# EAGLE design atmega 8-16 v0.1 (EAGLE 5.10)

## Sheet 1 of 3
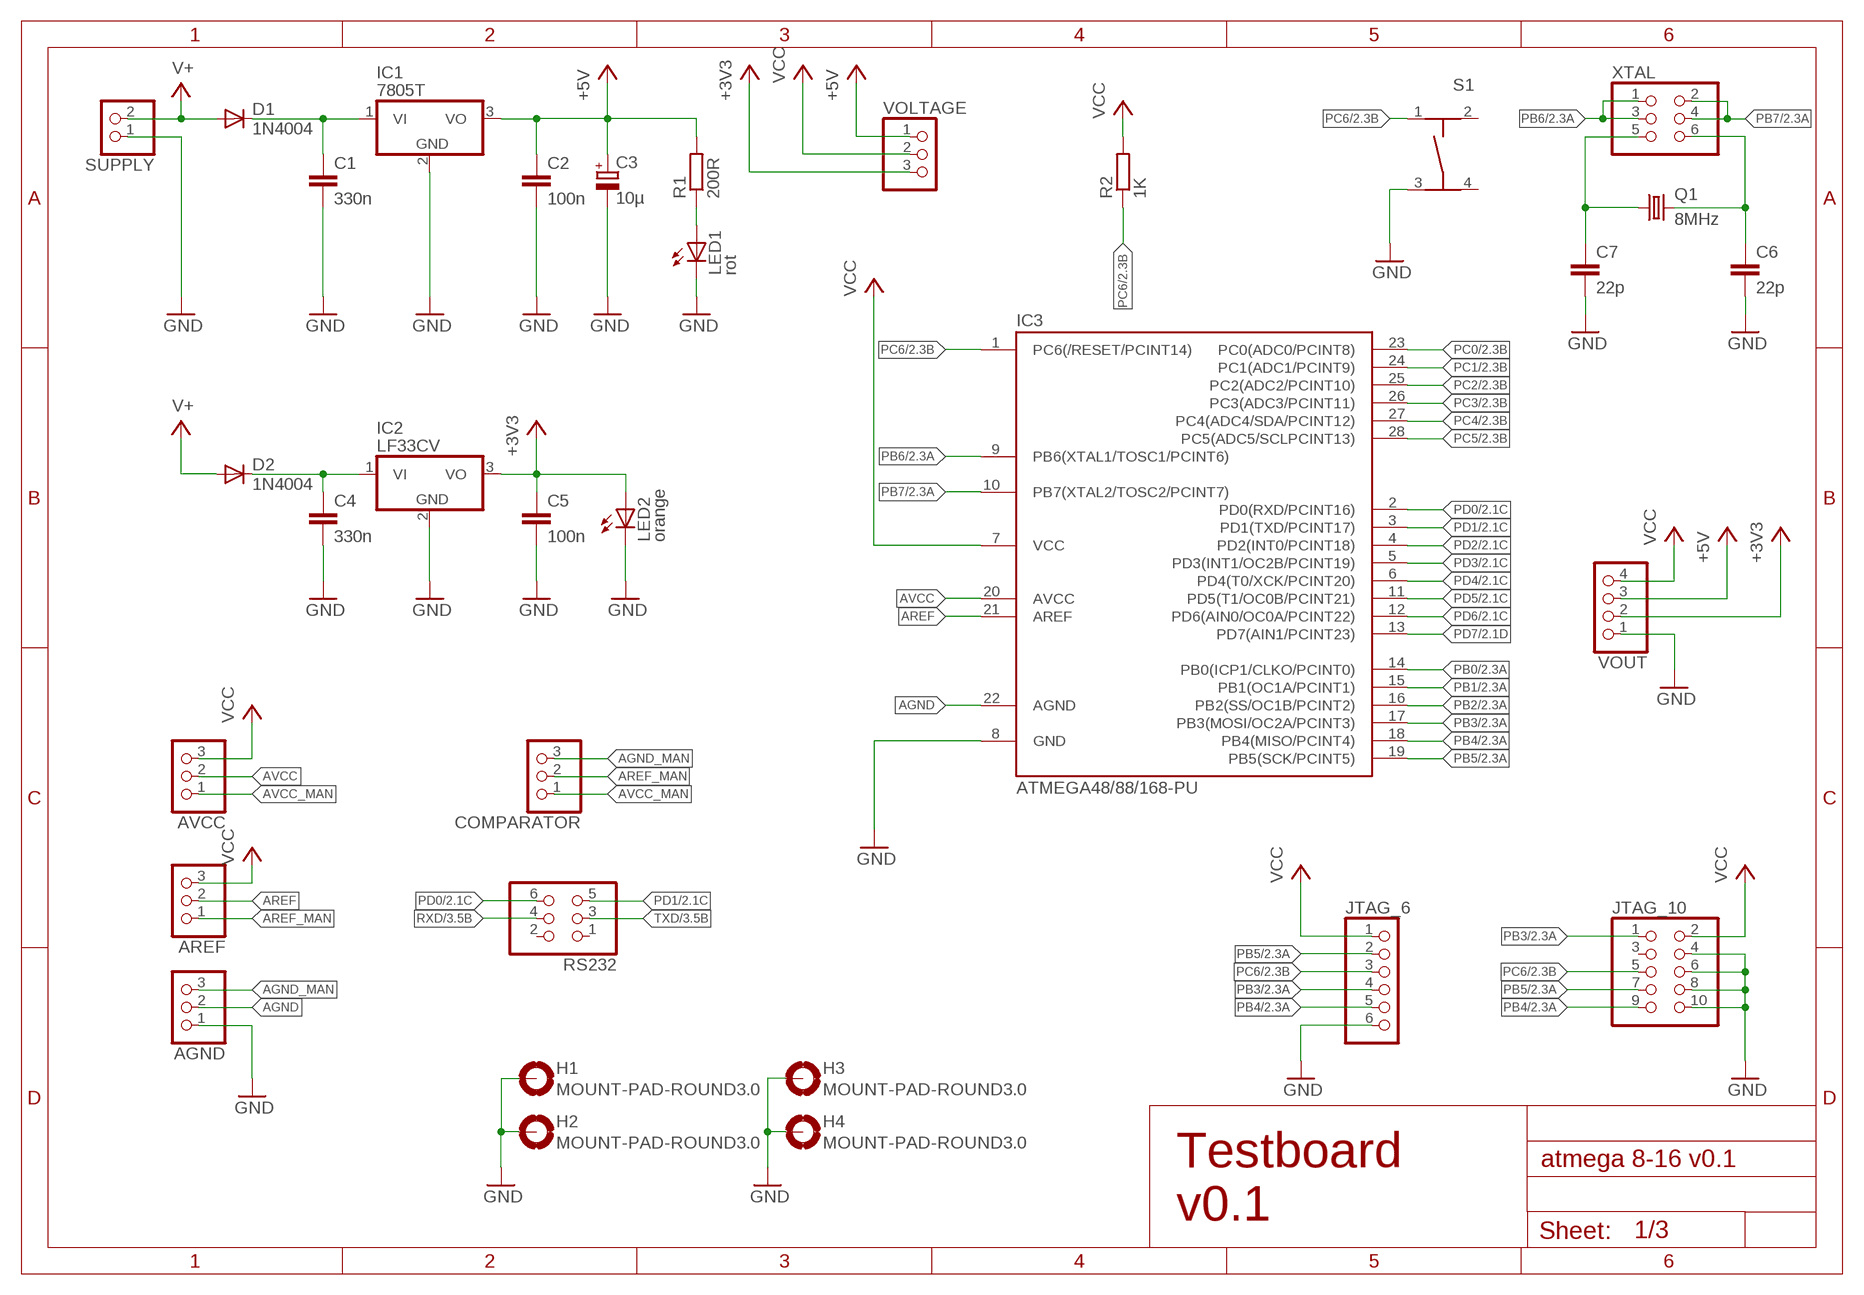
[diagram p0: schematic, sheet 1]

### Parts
AGND  PINHD-1X3  [1X03]
AREF  PINHD-1X3  [1X03]
AVCC  PINHD-1X3  [1X03]
C1  330n  C-EU025-030X050  [C025-030X050]
C2  100n  C-EU025-030X050  [C025-030X050]
C3  10µ  CPOL-EUE2.5-5  [E2,5-5]
C4  330n  C-EU025-030X050  [C025-030X050]
C5  100n  C-EU025-030X050  [C025-030X050]
C6  22p  C-EU025-030X050  [C025-030X050]
C7  22p  C-EU025-030X050  [C025-030X050]
COMPARATOR  PINHD-1X3  [1X03]
D1  1N4004  [DO41-10]
D2  1N4004  [DO41-10]
H1  MOUNT-PAD-ROUND3.0  [3,0-PAD]
H2  MOUNT-PAD-ROUND3.0  [3,0-PAD]
H3  MOUNT-PAD-ROUND3.0  [3,0-PAD]
H4  MOUNT-PAD-ROUND3.0  [3,0-PAD]
IC1  7805T  [TO220H]
IC2  LF33CV  7805T  [TO220H]
IC3  ATMEGA48/88/168-PU  [DIL28-3]
JTAG_6  PINHD-1X6  [1X06]
JTAG_10  PINHD-2X5  [2X05]
LED1  rot  LED3MM  [LED3MM]
LED2  orange  LED3MM  [LED3MM]
Q1  8MHz  CRYSTALHC18U-V  [HC18U-V]
R1  200R  R-EU_0207/12  [0207/12]
R2  1K  R-EU_0207/12  [0207/12]
RS232  PINHD-2X3  [2X03]
S1  TASTER-9314_SMD  [TASTER-9314_SMD]
SUPPLY  PINHD-1X2  [1X02]
VOLTAGE  PINHD-1X3  [1X03]
VOUT  PINHD-1X4  [1X04]
XTAL  PINHD-2X3  [2X03]

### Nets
+3V3: C5.1 IC2.3(VO) LED2.A VOLTAGE.3 VOUT.2
+5V: C2.1 C3.+ IC1.3(VO) R1.2 VOLTAGE.1 VOUT.3 ; also sheet 3
AGND: AGND.2 IC3.22(AGND)
AGND_MAN: AGND.3 COMPARATOR.3
AREF: AREF.2 IC3.21(AREF)
AREF_MAN: AREF.1 COMPARATOR.2
AVCC: AVCC.2 IC3.20(AVCC)
AVCC_MAN: AVCC.1 COMPARATOR.1
GND: AGND.1 C1.2 C2.2 C3.- C4.2 C5.2 C6.2 C7.2 H1.B3,0(MOUNT) H2.B3,0(MOUNT) H3.B3,0(MOUNT) H4.B3,0(MOUNT) IC1.2(GND) IC2.2(GND) IC3.8(GND) JTAG_6.6 JTAG_10.4 JTAG_10.6 JTAG_10.8 JTAG_10.10 LED1.K(C) LED2.K(C) S1.3 SUPPLY.1 VOUT.1 ; also sheet 2,3
N$1: C4.1 D2.C IC2.1(VI)
N$3: C7.1 Q1.1 XTAL.5
N$4: C1.1 D1.C IC1.1(VI)
N$5: LED1.A R1.1
N$6: C6.1 Q1.2 XTAL.6
PB0: IC3.14(PB0(ICP1/CLKO/PCINT0)) ; also sheet 2
PB1: IC3.15(PB1(OC1A/PCINT1)) ; also sheet 2
PB2: IC3.16(PB2(SS/OC1B/PCINT2)) ; also sheet 2
PB3: IC3.17(PB3(MOSI/OC2A/PCINT3)) JTAG_6.4 JTAG_10.1 ; also sheet 2
PB4: IC3.18(PB4(MISO/PCINT4)) JTAG_6.5 JTAG_10.9 ; also sheet 2
PB5: IC3.19(PB5(SCK/PCINT5)) JTAG_6.2 JTAG_10.7 ; also sheet 2
PB6: IC3.9(PB6(XTAL1/TOSC1/PCINT6)) XTAL.1 XTAL.3 ; also sheet 2
PB7: IC3.10(PB7(XTAL2/TOSC2/PCINT7)) XTAL.2 XTAL.4 ; also sheet 2
PC0: IC3.23(PC0(ADC0/PCINT8)) ; also sheet 2,3
PC1: IC3.24(PC1(ADC1/PCINT9)) ; also sheet 2,3
PC2: IC3.25(PC2(ADC2/PCINT10)) ; also sheet 2,3
PC3: IC3.26(PC3(ADC3/PCINT11)) ; also sheet 2,3
PC4: IC3.27(PC4(ADC4/SDA/PCINT12)) ; also sheet 2,3
PC5: IC3.28(PC5(ADC5/SCLPCINT13)) ; also sheet 2,3
PC6: IC3.1(PC6(/RESET/PCINT14)) JTAG_6.3 JTAG_10.5 R2.1 S1.1 ; also sheet 2
PD0: IC3.2(PD0(RXD/PCINT16)) RS232.6 ; also sheet 2
PD1: IC3.3(PD1(TXD/PCINT17)) RS232.5 ; also sheet 2
PD2: IC3.4(PD2(INT0/PCINT18)) ; also sheet 2,3
PD3: IC3.5(PD3(INT1/OC2B/PCINT19)) ; also sheet 2
PD4: IC3.6(PD4(T0/XCK/PCINT20)) ; also sheet 2
PD5: IC3.11(PD5(T1/OC0B/PCINT21)) ; also sheet 2
PD6: IC3.12(PD6(AIN0/OC0A/PCINT22)) ; also sheet 2,3
PD7: IC3.13(PD7(AIN1/PCINT23)) ; also sheet 2,3
RXD: RS232.4 ; also sheet 3
TXD: RS232.3 ; also sheet 3
V+: D1.A D2.A SUPPLY.2
VCC: AREF.3 AVCC.3 IC3.7(VCC) JTAG_6.1 JTAG_10.2 R2.2 VOLTAGE.2 VOUT.4 ; also sheet 3
Unconnected: JTAG_10.3 RS232.1 RS232.2 S1.2 S1.4

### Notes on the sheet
- Testboard
- v0.1

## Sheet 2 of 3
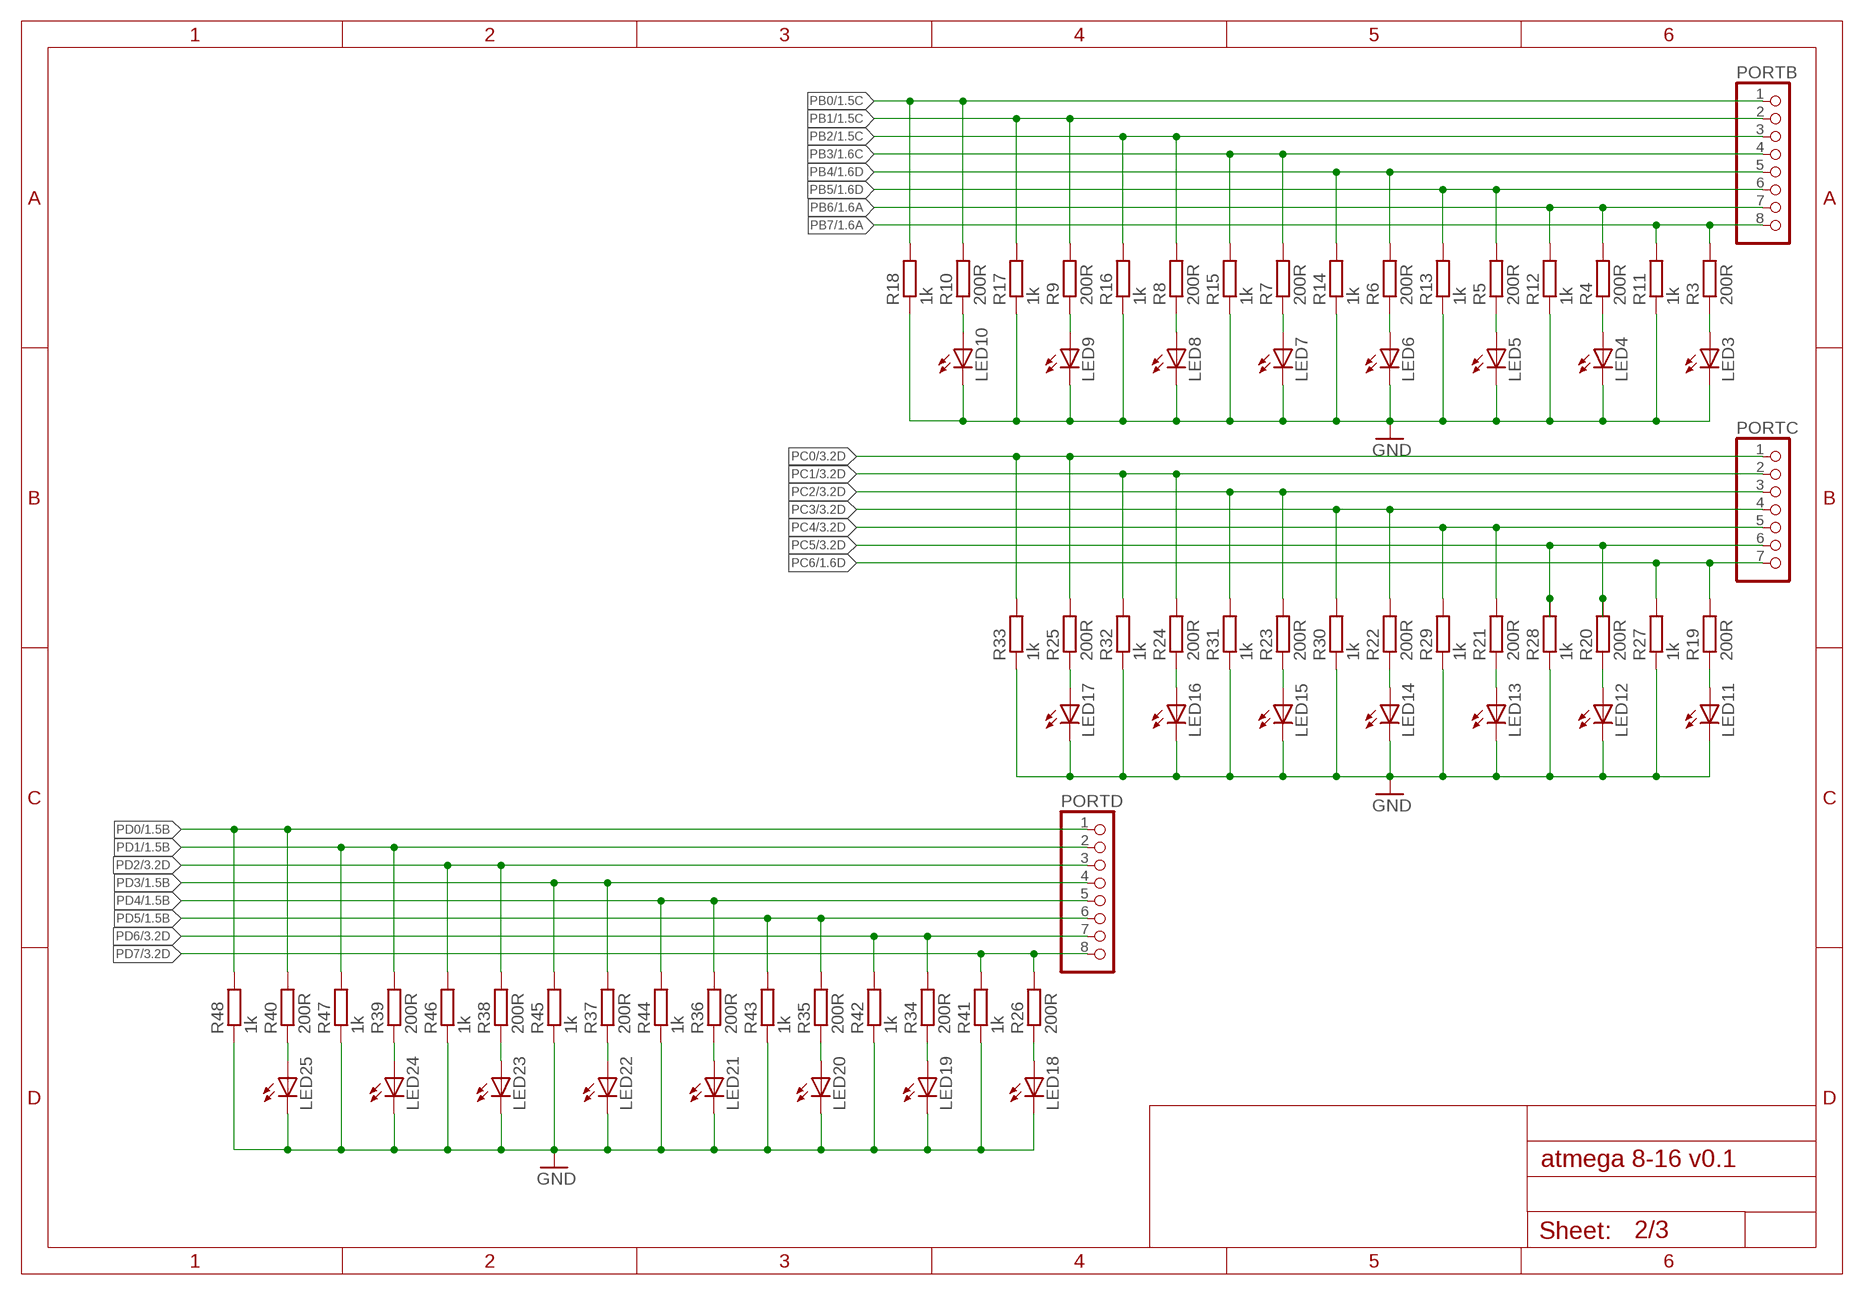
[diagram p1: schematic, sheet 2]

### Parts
LED3  LED3MM  [LED3MM]
LED4  LED3MM  [LED3MM]
LED5  LED3MM  [LED3MM]
LED6  LED3MM  [LED3MM]
LED7  LED3MM  [LED3MM]
LED8  LED3MM  [LED3MM]
LED9  LED3MM  [LED3MM]
LED10  LED3MM  [LED3MM]
LED11  LED3MM  [LED3MM]
LED12  LED3MM  [LED3MM]
LED13  LED3MM  [LED3MM]
LED14  LED3MM  [LED3MM]
LED15  LED3MM  [LED3MM]
LED16  LED3MM  [LED3MM]
LED17  LED3MM  [LED3MM]
LED18  LED3MM  [LED3MM]
LED19  LED3MM  [LED3MM]
LED20  LED3MM  [LED3MM]
LED21  LED3MM  [LED3MM]
LED22  LED3MM  [LED3MM]
LED23  LED3MM  [LED3MM]
LED24  LED3MM  [LED3MM]
LED25  LED3MM  [LED3MM]
PORTB  PINHD-1X8  [1X08]
PORTC  PINHD-1X7  [1X07]
PORTD  PINHD-1X8  [1X08]
R3  200R  R-EU_0207/12  [0207/12]
R4  200R  R-EU_0207/12  [0207/12]
R5  200R  R-EU_0207/12  [0207/12]
R6  200R  R-EU_0207/12  [0207/12]
R7  200R  R-EU_0207/12  [0207/12]
R8  200R  R-EU_0207/12  [0207/12]
R9  200R  R-EU_0207/12  [0207/12]
R10  200R  R-EU_0207/12  [0207/12]
R11  1k  R-EU_0207/12  [0207/12]
R12  1k  R-EU_0207/12  [0207/12]
R13  1k  R-EU_0207/12  [0207/12]
R14  1k  R-EU_0207/12  [0207/12]
R15  1k  R-EU_0207/12  [0207/12]
R16  1k  R-EU_0207/12  [0207/12]
R17  1k  R-EU_0207/12  [0207/12]
R18  1k  R-EU_0207/12  [0207/12]
R19  200R  R-EU_0207/12  [0207/12]
R20  200R  R-EU_0207/12  [0207/12]
R21  200R  R-EU_0207/12  [0207/12]
R22  200R  R-EU_0207/12  [0207/12]
R23  200R  R-EU_0207/12  [0207/12]
R24  200R  R-EU_0207/12  [0207/12]
R25  200R  R-EU_0207/12  [0207/12]
R26  200R  R-EU_0207/12  [0207/12]
R27  1k  R-EU_0207/12  [0207/12]
R28  1k  R-EU_0207/12  [0207/12]
R29  1k  R-EU_0207/12  [0207/12]
R30  1k  R-EU_0207/12  [0207/12]
R31  1k  R-EU_0207/12  [0207/12]
R32  1k  R-EU_0207/12  [0207/12]
R33  1k  R-EU_0207/12  [0207/12]
R34  200R  R-EU_0207/12  [0207/12]
R35  200R  R-EU_0207/12  [0207/12]
R36  200R  R-EU_0207/12  [0207/12]
R37  200R  R-EU_0207/12  [0207/12]
R38  200R  R-EU_0207/12  [0207/12]
R39  200R  R-EU_0207/12  [0207/12]
R40  200R  R-EU_0207/12  [0207/12]
R41  1k  R-EU_0207/12  [0207/12]
R42  1k  R-EU_0207/12  [0207/12]
R43  1k  R-EU_0207/12  [0207/12]
R44  1k  R-EU_0207/12  [0207/12]
R45  1k  R-EU_0207/12  [0207/12]
R46  1k  R-EU_0207/12  [0207/12]
R47  1k  R-EU_0207/12  [0207/12]
R48  1k  R-EU_0207/12  [0207/12]

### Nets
GND: LED3.K(C) LED4.K(C) LED5.K(C) LED6.K(C) LED7.K(C) LED8.K(C) LED9.K(C) LED10.K(C) LED11.K(C) LED12.K(C) LED13.K(C) LED14.K(C) LED15.K(C) LED16.K(C) LED17.K(C) LED18.K(C) LED19.K(C) LED20.K(C) LED21.K(C) LED22.K(C) LED23.K(C) LED24.K(C) LED25.K(C) R11.1 R12.1 R13.1 R14.1 R15.1 R16.1 R17.1 R18.1 R27.1 R28.1 R29.1 R30.1 R31.1 R32.1 R33.1 R41.1 R42.1 R43.1 R44.1 R45.1 R46.1 R47.1 R48.1 ; also sheet 1,3
N$7: LED7.A R7.1
N$8: LED9.A R9.1
N$9: LED10.A R10.1
N$10: LED8.A R8.1
N$11: LED6.A R6.1
N$12: LED5.A R5.1
N$13: LED4.A R4.1
N$14: LED3.A R3.1
N$16: LED15.A R23.1
N$17: LED17.A R25.1
N$18: LED22.A R37.1
N$19: LED16.A R24.1
N$20: LED14.A R22.1
N$21: LED13.A R21.1
N$22: LED12.A R20.1
N$23: LED11.A R19.1
N$25: LED24.A R39.1
N$26: LED25.A R40.1
N$27: LED23.A R38.1
N$28: LED21.A R36.1
N$29: LED20.A R35.1
N$30: LED19.A R34.1
N$31: LED18.A R26.1
PB0: PORTB.1 R10.2 R18.2 ; also sheet 1
PB1: PORTB.2 R9.2 R17.2 ; also sheet 1
PB2: PORTB.3 R8.2 R16.2 ; also sheet 1
PB3: PORTB.4 R7.2 R15.2 ; also sheet 1
PB4: PORTB.5 R6.2 R14.2 ; also sheet 1
PB5: PORTB.6 R5.2 R13.2 ; also sheet 1
PB6: PORTB.7 R4.2 R12.2 ; also sheet 1
PB7: PORTB.8 R3.2 R11.2 ; also sheet 1
PC0: PORTC.1 R25.2 R33.2 ; also sheet 1,3
PC1: PORTC.2 R24.2 R32.2 ; also sheet 1,3
PC2: PORTC.3 R23.2 R31.2 ; also sheet 1,3
PC3: PORTC.4 R22.2 R30.2 ; also sheet 1,3
PC4: PORTC.5 R21.2 R29.2 ; also sheet 1,3
PC5: PORTC.6 R20.2 R28.2 ; also sheet 1,3
PC6: PORTC.7 R19.2 R27.2 ; also sheet 1
PD0: PORTD.1 R40.2 R48.2 ; also sheet 1
PD1: PORTD.2 R39.2 R47.2 ; also sheet 1
PD2: PORTD.3 R38.2 R46.2 ; also sheet 1,3
PD3: PORTD.4 R37.2 R45.2 ; also sheet 1
PD4: PORTD.5 R36.2 R44.2 ; also sheet 1
PD5: PORTD.6 R35.2 R43.2 ; also sheet 1
PD6: PORTD.7 R34.2 R42.2 ; also sheet 1,3
PD7: PORTD.8 R26.2 R41.2 ; also sheet 1,3

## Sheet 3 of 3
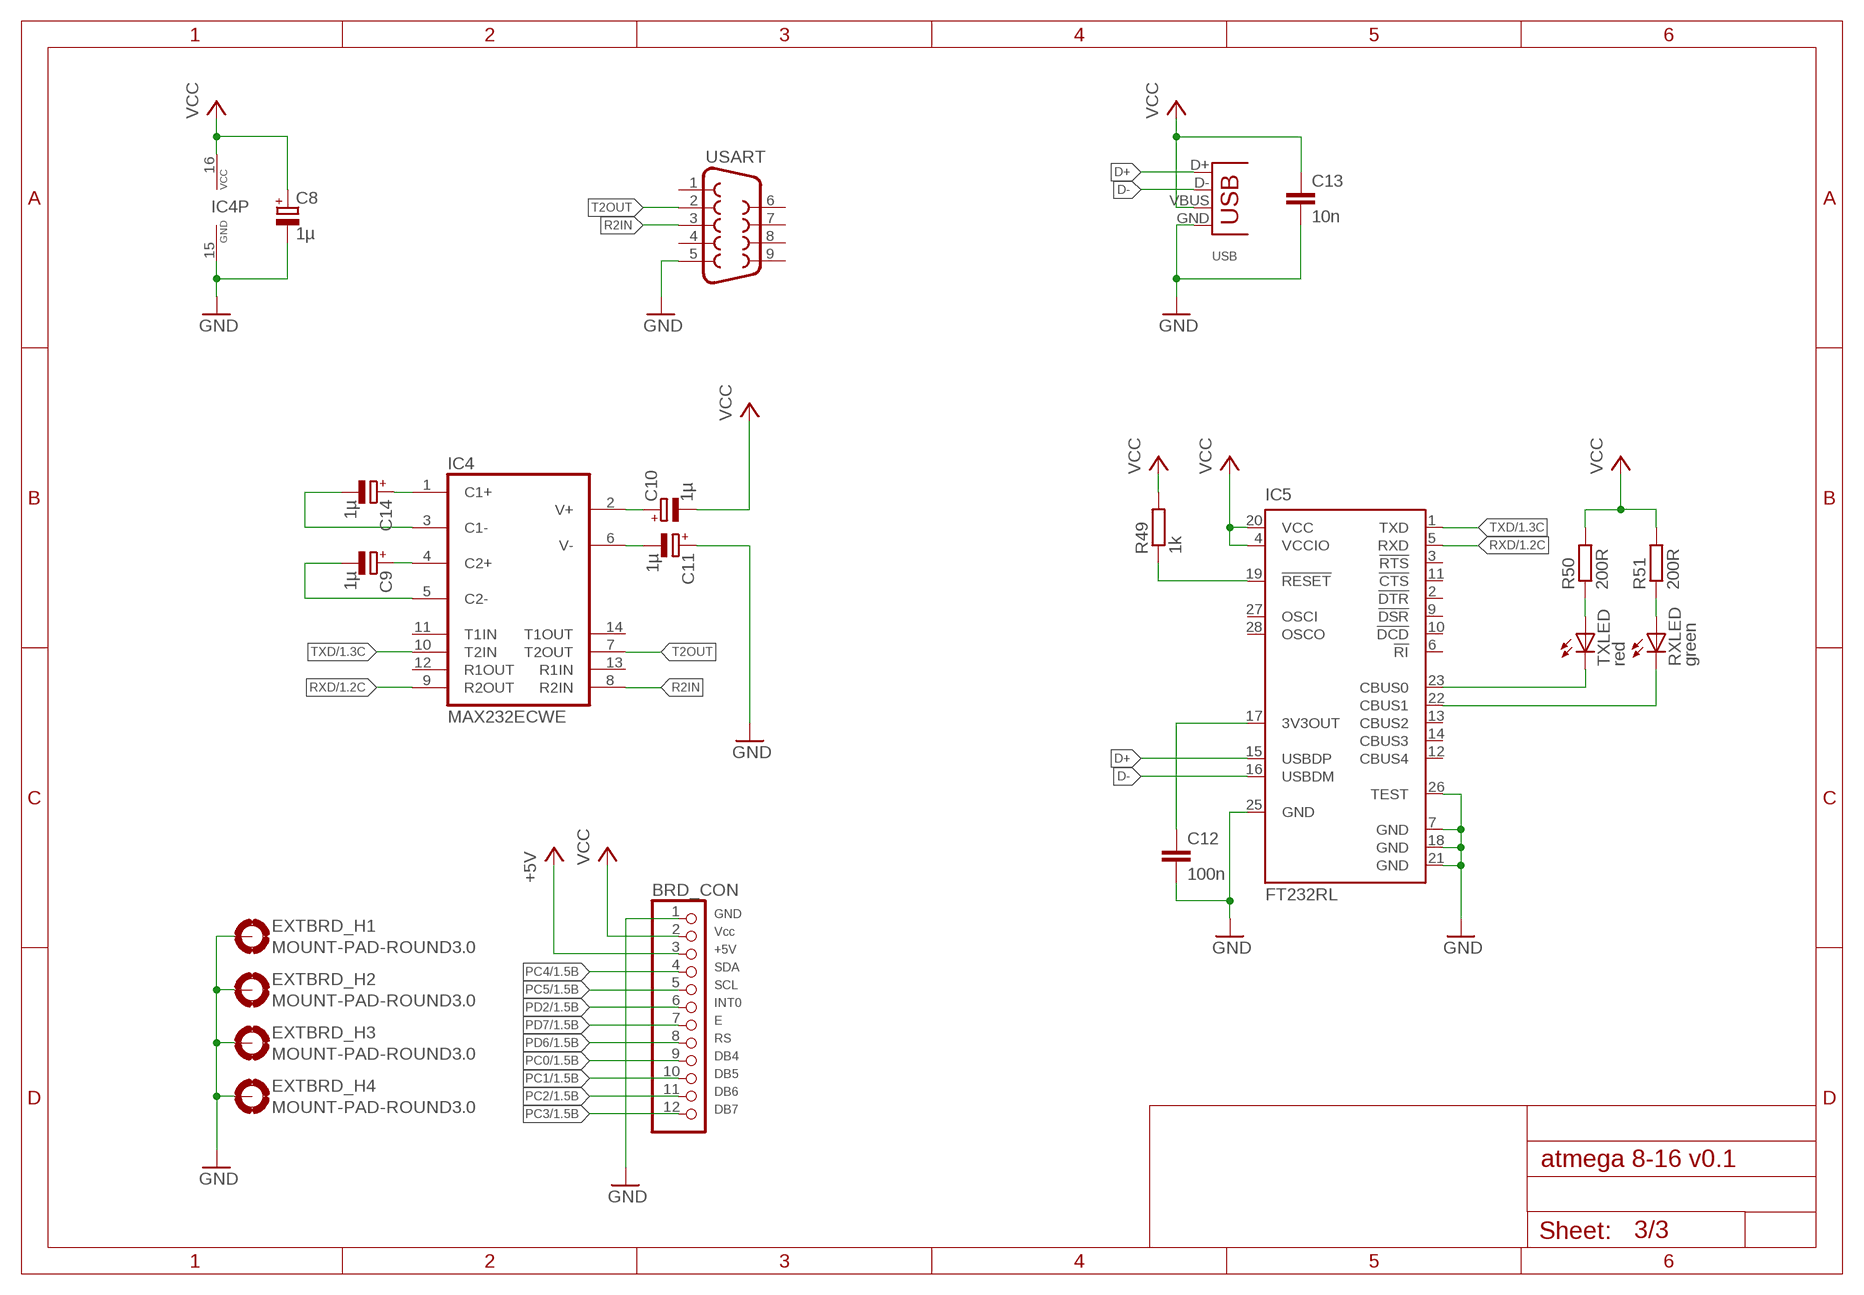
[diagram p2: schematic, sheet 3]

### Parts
BRD_CON  PINHD-1X12  [1X12]
C8  1µ  CPOL-EUE2.5-5  [E2,5-5]
C9  1µ  CPOL-EUE2.5-5  [E2,5-5]
C10  1µ  CPOL-EUE2.5-5  [E2,5-5]
C11  1µ  CPOL-EUE2.5-5  [E2,5-5]
C12  100n  C-EU025-040X050  [C025-040X050]
C13  10n  C-EU025-040X050  [C025-040X050]
C14  1µ  CPOL-EUE2.5-5  [E2,5-5]
EXTBRD_H1  MOUNT-PAD-ROUND3.0  [3,0-PAD]
EXTBRD_H2  MOUNT-PAD-ROUND3.0  [3,0-PAD]
EXTBRD_H3  MOUNT-PAD-ROUND3.0  [3,0-PAD]
EXTBRD_H4  MOUNT-PAD-ROUND3.0  [3,0-PAD]
IC4  MAX232ECWE  [SO16L]
IC5  FT232RL  [SSOP28]
R49  1k  R-EU_0207/2V  [0207/2V]
R50  200R  R-EU_0207/12  [0207/12]
R51  200R  R-EU_0207/12  [0207/12]
RXLED  green  LED3MM  [LED3MM]
TXLED  red  LED3MM  [LED3MM]
USART  F09HP  [F09HP]
USB  USB-B-H  [USB-B-H]

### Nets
+5V: BRD_CON.3 ; also sheet 1
D+: IC5.15(USBDP) USB.D+
D-: IC5.16(USBDM) USB.D-
GND: BRD_CON.1 C8.- C11.+ C12.2 C13.2 EXTBRD_H1.B3,0(MOUNT) EXTBRD_H2.B3,0(MOUNT) EXTBRD_H3.B3,0(MOUNT) EXTBRD_H4.B3,0(MOUNT) IC4.15(GND) IC5.7(GND) IC5.18(GND) IC5.21(GND) IC5.25(GND) IC5.26(TEST) USART.5 USB.GND ; also sheet 1,2
N$2: C14.- IC4.3(C1-)
N$15: C14.+ IC4.1(C1+)
N$33: C10.+ IC4.2(V+)
N$34: C11.- IC4.6(V-)
N$35: C9.+ IC4.4(C2+)
N$36: C9.- IC4.5(C2-)
N$37: IC5.19(!RESET) R49.1
N$38: C12.1 IC5.17(3V3OUT)
N$41: R50.1 TXLED.A
N$42: R51.1 RXLED.A
N$43: IC5.23(CBUS0) TXLED.K(C)
N$44: IC5.22(CBUS1) RXLED.K(C)
PC0: BRD_CON.9 ; also sheet 1,2
PC1: BRD_CON.10 ; also sheet 1,2
PC2: BRD_CON.11 ; also sheet 1,2
PC3: BRD_CON.12 ; also sheet 1,2
PC4: BRD_CON.4 ; also sheet 1,2
PC5: BRD_CON.5 ; also sheet 1,2
PD2: BRD_CON.6 ; also sheet 1,2
PD6: BRD_CON.8 ; also sheet 1,2
PD7: BRD_CON.7 ; also sheet 1,2
R2IN: IC4.8(R2IN) USART.3
RXD: IC4.9(R2OUT) IC5.5(RXD) ; also sheet 1
T2OUT: IC4.7(T2OUT) USART.2
TXD: IC4.10(T2IN) IC5.1(TXD) ; also sheet 1
VCC: BRD_CON.2 C8.+ C10.- C13.1 IC4.16(VCC) IC5.4(VCCIO) IC5.20(VCC) R49.2 R50.2 R51.2 USB.VBUS ; also sheet 1
Unconnected: IC4.11(T1IN) IC4.12(R1OUT) IC4.13(R1IN) IC4.14(T1OUT) IC5.2(!DTR) IC5.3(!RTS) IC5.6(!RI) IC5.9(!DSR) IC5.10(!DCD) IC5.11(!CTS) IC5.12(CBUS4) IC5.13(CBUS2) IC5.14(CBUS3) IC5.27(OSCI) IC5.28(OSCO) USART.1 USART.4 USART.6 USART.7 USART.8 USART.9

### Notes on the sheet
- GND
- Vcc
- +5V
- SDA
- SCL
- INT0
- E
- RS
- DB4
- DB5
- DB6
- DB7

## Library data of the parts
AGND AREF AVCC COMPARATOR VOLTAGE = pinhead:PINHD-1X3: PIN HEADER
BRD_CON = pinhead:PINHD-1X12: PIN HEADER
C1 C2 C4-C7 C12 C13 = rcl:C-EU: CAPACITOR, European symbol
C3 C8-C11 C14 = rcl:CPOL-EU: POLARIZED CAPACITOR, European symbol
D1 D2 = diode:1N4004: DIODE
EXTBRD_H1-EXTBRD_H4 H1-H4 = holes:MOUNT-PAD-ROUND: MOUNTING PAD, round
IC1 IC2 = linear:78*: Positive VOLTAGE REGULATOR Source: http://cache.national.com/ds/LM/LM78L05.pdf http://www.fairchildsemi.com/ds/LM/LM7805.pdf
IC3 = atmega8:ATMEGA48/88/168-PU
IC4 = maxim:MAX232ECWE: RS232 TRANSEIVER
IC5 = ftdichip:FT232R: Source: http://www.ftdichip.com/Documents/DataSheets/DS_FT232R_v104.pdf
JTAG_6 = pinhead:PINHD-1X6: PIN HEADER
JTAG_10 = pinhead:PINHD-2X5: PIN HEADER
LED1-LED25 RXLED TXLED = led:LED: LED
PORTB PORTD = pinhead:PINHD-1X8: PIN HEADER
PORTC = pinhead:PINHD-1X7: PIN HEADER
Q1 = crystal:CRYSTAL: CRYSTAL
R1-R51 = rcl:R-EU_: RESISTOR, European symbol
RS232 XTAL = pinhead:PINHD-2X3: PIN HEADER
S1 = Ergaenzung_Taster:TASTER-9314_SMD
SUPPLY = pinhead:PINHD-1X2: PIN HEADER
USART = con-subd:F09: SUB-D
USB = con-usb-3:USB: USB Connectors
VOUT = pinhead:PINHD-1X4: PIN HEADER

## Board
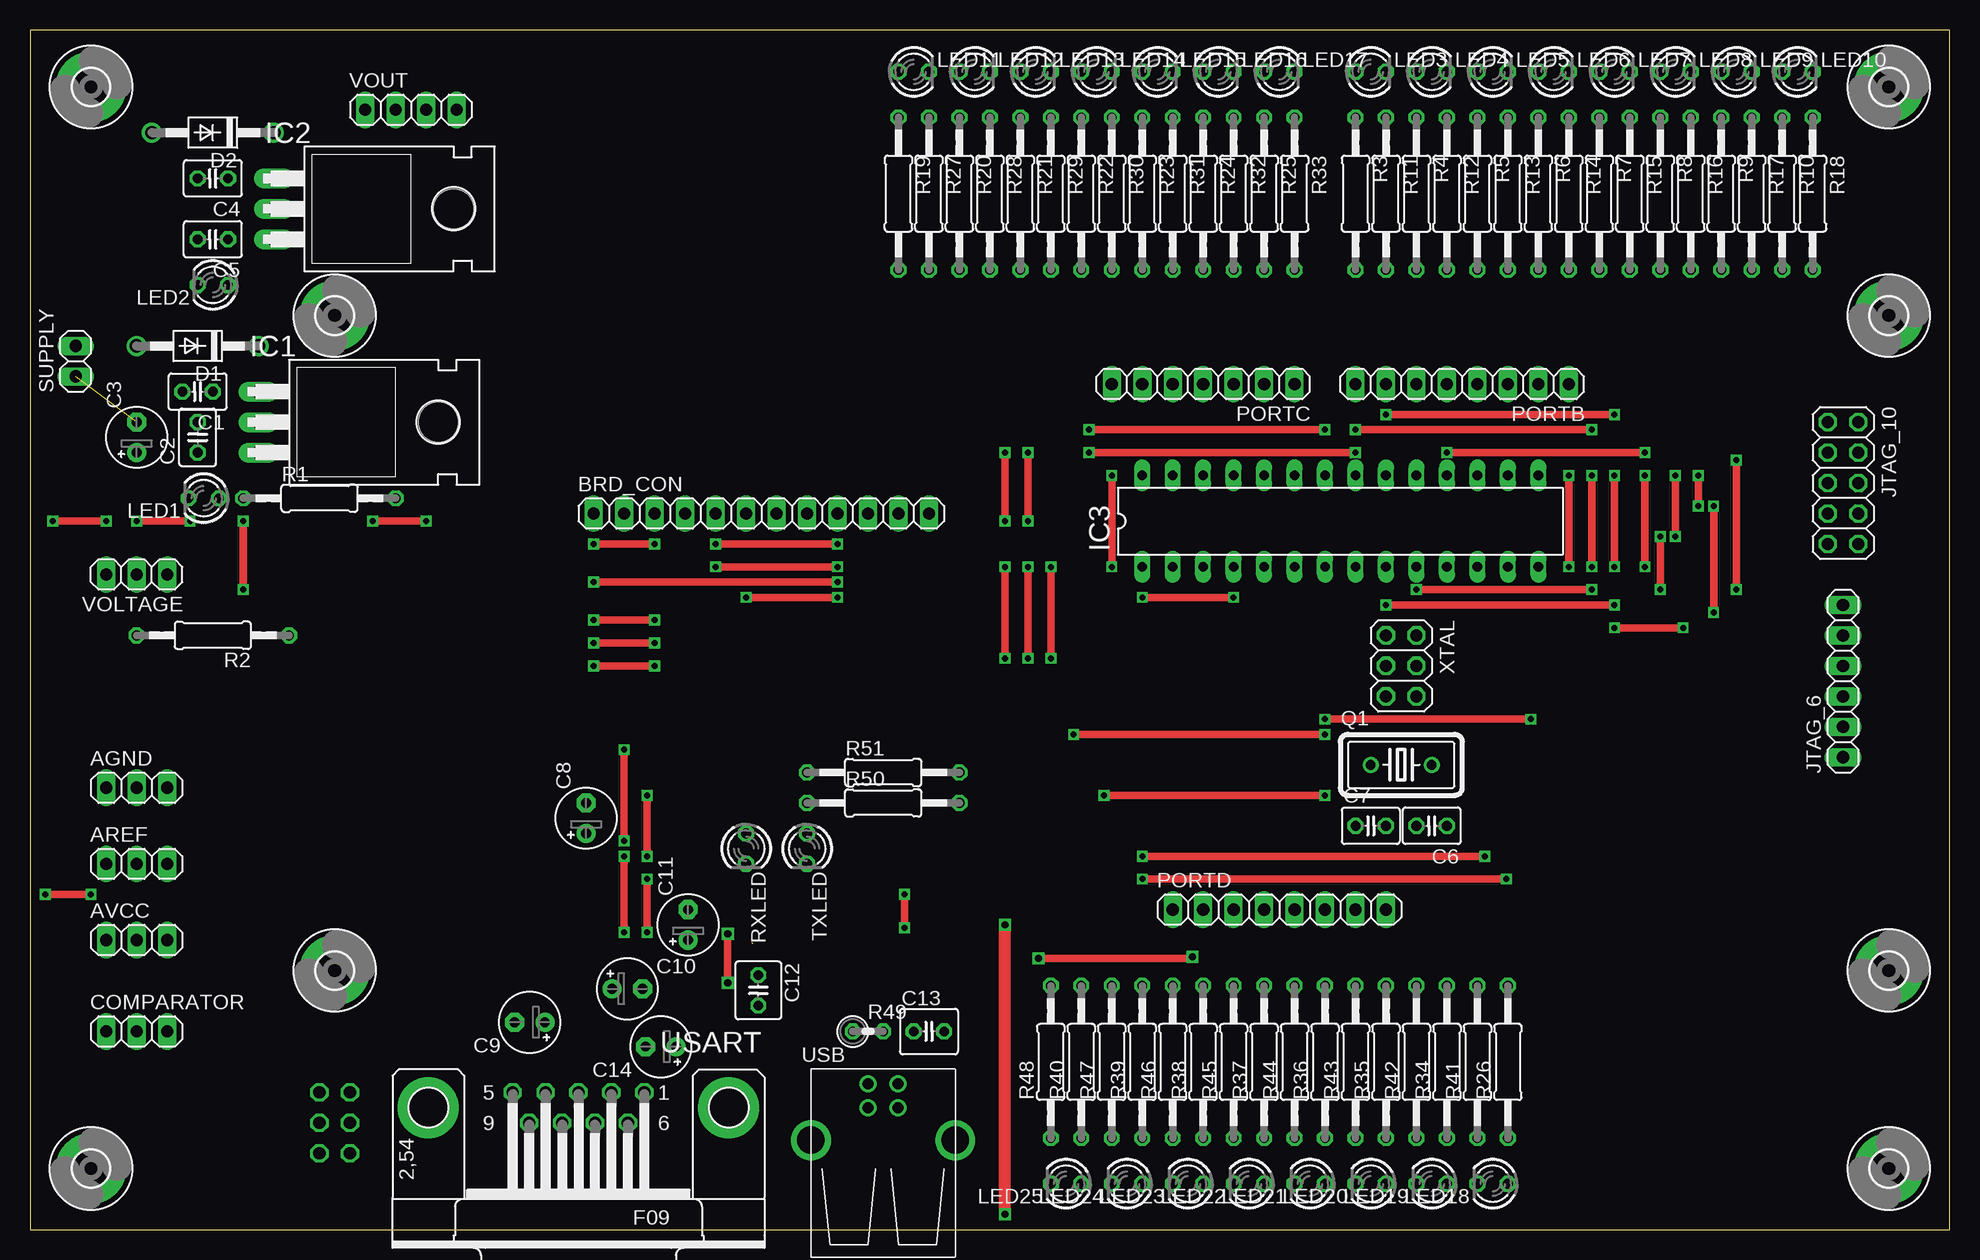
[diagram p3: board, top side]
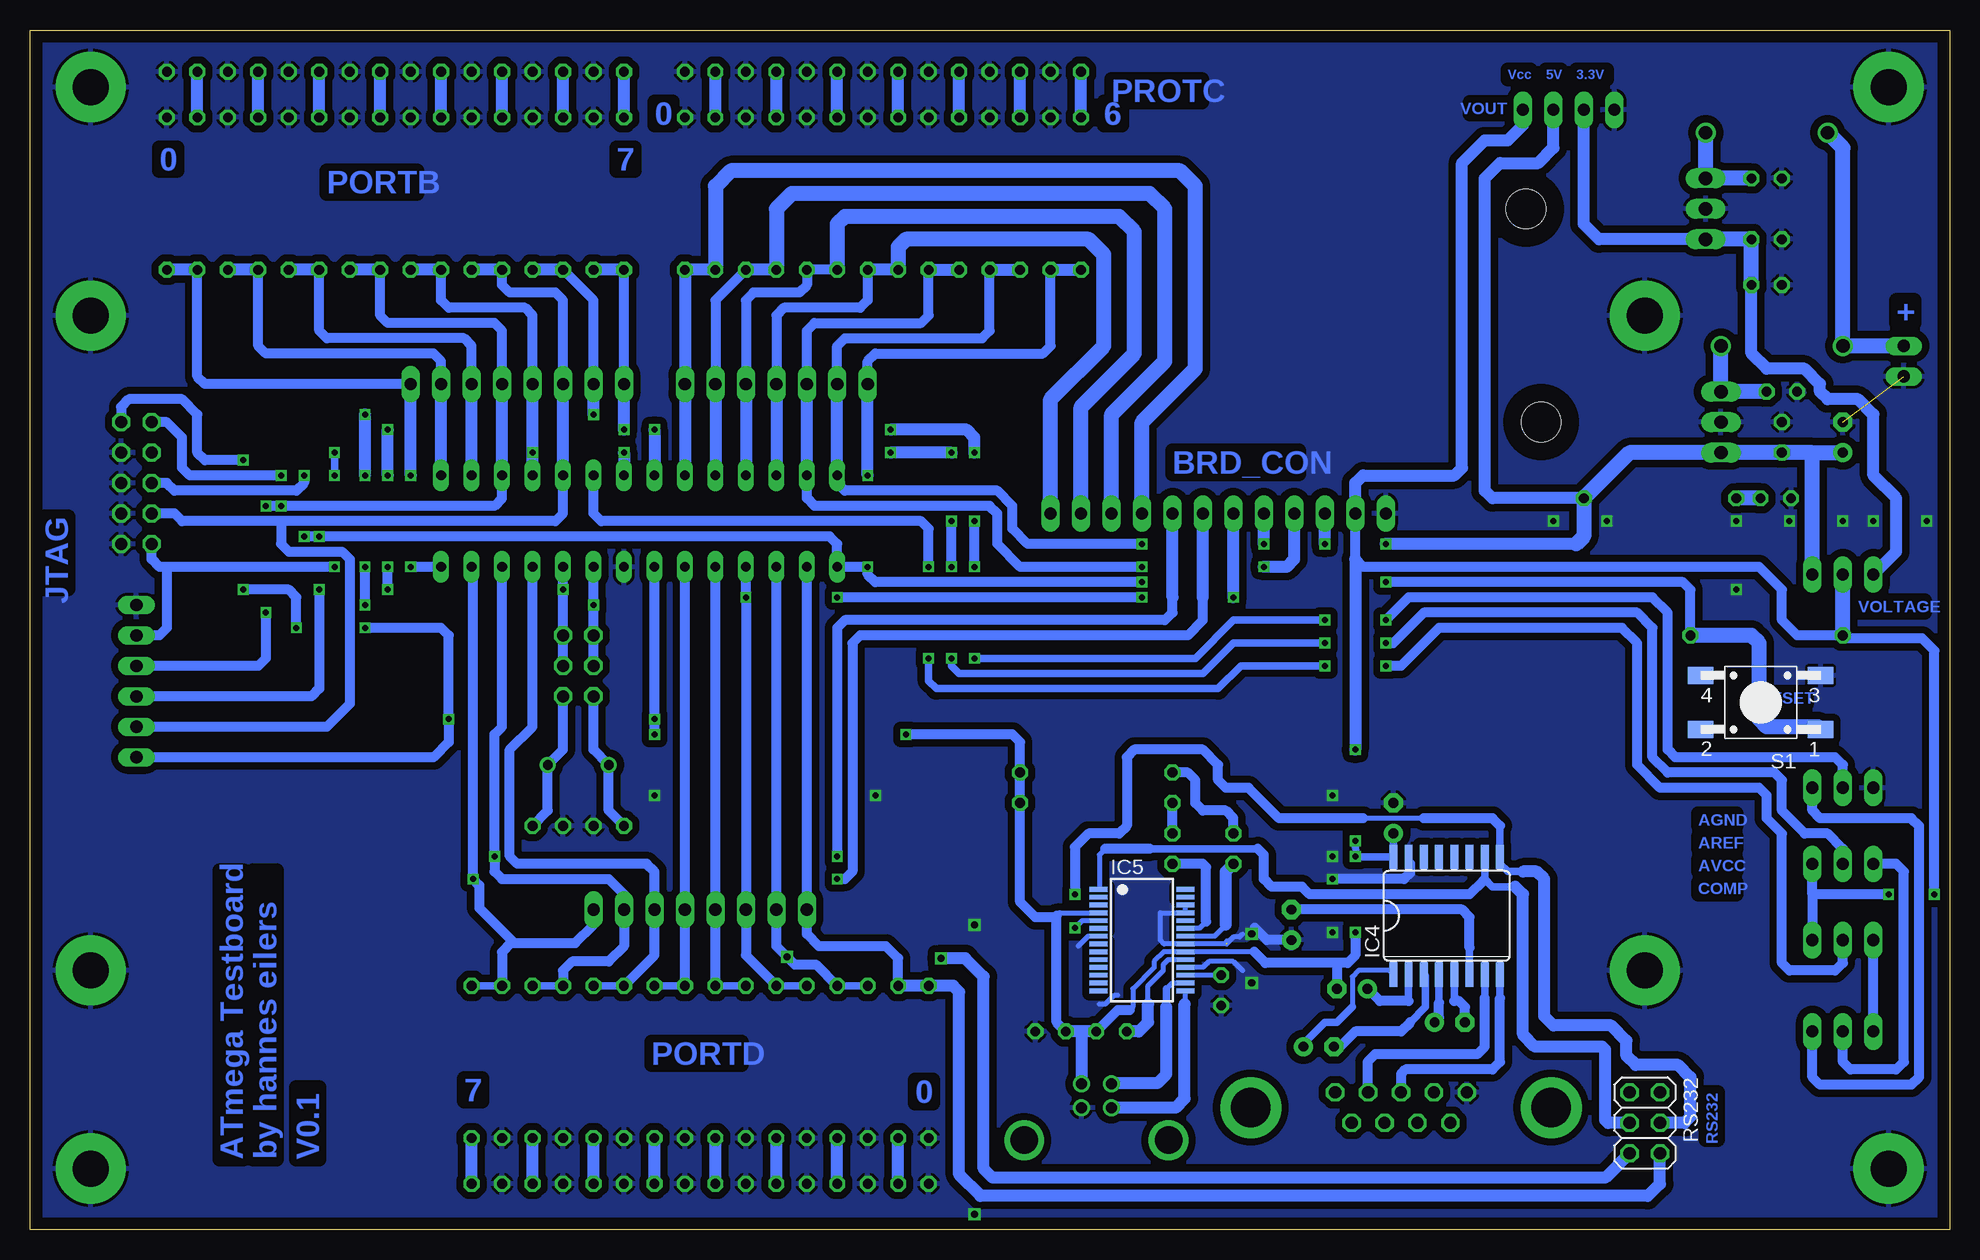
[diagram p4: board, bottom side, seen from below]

Size 160 x 100 mm. Coordinates in mm from the lower left corner, seen from the top.
Outline: 0,0 160,0 160,100 0,100 0,0
Copper layers (1*16): Top 0.035mm / dielectric 1.5mm / Bottom 0.035mm
Design rules "default": minimum track width 10mil, minimum drill 24mil, track to track 8mil, track to pad 8mil, pad to pad 8mil, via to via 8mil, smd to smd 8mil, copper to edge 40mil, drill to drill 8mil, minimum pad ring 10mil, minimum via ring 8mil, stop-mask expansion 4mil, vias tented up to drill 0mil, thermal gap 10mil

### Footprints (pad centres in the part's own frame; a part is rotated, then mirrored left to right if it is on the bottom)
1X03 = drill 1.016 long: 1 -2.54,0; 2 0,0; 3 2.54,0
1X12 = drill 1.016 long: 1 -13.97,0; 2 -11.43,0; 3 -8.89,0; 4 -6.35,0; 5 -3.81,0; 6 -1.27,0; 7 1.27,0; 8 3.81,0; 9 6.35,0; 10 8.89,0; 11 11.43,0; 12 13.97,0
C025-030X050 = drill 0.813 octagon: 1 -1.27,0; 2 1.27,0
E2,5-5 = drill 0.813 pad 1.6 round: + -1.27,0 | drill 0.813 pad 1.6 octagon: - 1.27,0
C025-040X050 = drill 0.813 octagon: 1 -1.27,0; 2 1.27,0
DO41-10 = drill 1.118 round: A 5.08,0; C -5.08,0
3,0-PAD = drill 3 pad 5.842 round: B3,0 0,0
TO220H = drill 1.118 long: 1 -2.54,-10.16; 2 0,-10.16; 3 2.54,-10.16 | hole 3.302: 0,4.826
DIL28-3 = drill 0.813 long: 1 -16.51,-3.81; 2 -13.97,-3.81; 3 -11.43,-3.81; 4 -8.89,-3.81; 5 -6.35,-3.81; 6 -3.81,-3.81; 7 -1.27,-3.81; 8 1.27,-3.81; 9 3.81,-3.81; 10 6.35,-3.81; 11 8.89,-3.81; 12 11.43,-3.81; 13 13.97,-3.81; 14 16.51,-3.81; 15 16.51,3.81; 16 13.97,3.81; 17 11.43,3.81; 18 8.89,3.81; 19 6.35,3.81; 20 3.81,3.81; 21 1.27,3.81; 22 -1.27,3.81; 23 -3.81,3.81; 24 -6.35,3.81; 25 -8.89,3.81; 26 -11.43,3.81; 27 -13.97,3.81; 28 -16.51,3.81
SO16L = smd 0.66 x 2.032: 1 -4.445,-4.902; 2 -3.175,-4.902; 3 -1.905,-4.902; 4 -0.635,-4.902; 5 0.635,-4.902; 6 1.905,-4.902; 7 3.175,-4.902; 8 4.445,-4.902; 9 4.445,4.902; 10 3.175,4.902; 11 1.905,4.902; 12 0.635,4.902; 13 -0.635,4.902; 14 -1.905,4.902; 15 -3.175,4.902; 16 -4.445,4.902
SSOP28 = smd 0.4 x 1.5: 1 -4.225,-3.625; 2 -3.575,-3.625; 3 -2.925,-3.625; 4 -2.275,-3.625; 5 -1.625,-3.625; 6 -0.975,-3.625; 7 -0.325,-3.625; 8 0.325,-3.625; 9 0.975,-3.625; 10 1.625,-3.625; 11 2.275,-3.625; 12 2.925,-3.625; 13 3.575,-3.625; 14 4.225,-3.625; 15 4.225,3.625; 16 3.575,3.625; 17 2.925,3.625; 18 2.275,3.625; 19 1.625,3.625; 20 0.975,3.625; 21 0.325,3.625; 22 -0.325,3.625; 23 -0.975,3.625; 24 -1.625,3.625; 25 -2.275,3.625; 26 -2.925,3.625; 27 -3.575,3.625; 28 -4.225,3.625
1X06 = drill 1.016 long: 1 -6.35,0; 2 -3.81,0; 3 -1.27,0; 4 1.27,0; 5 3.81,0; 6 6.35,0
2X05 = drill 1.016 octagon: 1 -5.08,-1.27; 2 -5.08,1.27; 3 -2.54,-1.27; 4 -2.54,1.27; 5 0,-1.27; 6 0,1.27; 7 2.54,-1.27; 8 2.54,1.27; 9 5.08,-1.27; 10 5.08,1.27
LED3MM = drill 0.813 octagon: A -1.27,0; K 1.27,0
1X08 = drill 1.016 long: 1 -8.89,0; 2 -6.35,0; 3 -3.81,0; 4 -1.27,0; 5 1.27,0; 6 3.81,0; 7 6.35,0; 8 8.89,0
1X07 = drill 1.016 long: 1 -7.62,0; 2 -5.08,0; 3 -2.54,0; 4 0,0; 5 2.54,0; 6 5.08,0; 7 7.62,0
HC18U-V = drill 0.813 round: 1 -2.54,0; 2 2.54,0
0207/12 = drill 0.813 octagon: 1 -6.35,0; 2 6.35,0
0207/2V = drill 0.813 octagon: 1 -1.27,0; 2 1.27,0
2X03 = drill 1.016 octagon: 1 -2.54,-1.27; 2 -2.54,1.27; 3 0,-1.27; 4 0,1.27; 5 2.54,-1.27; 6 2.54,1.27
TASTER-9314_SMD = smd 2.1 x 1.4: 1 -5,2.25; 2 5,2.25; 3 -5,-2.25; 4 5,-2.25
1X02 = drill 1.016 long: 1 -1.27,0; 2 1.27,0
F09HP = drill 1.016 octagon: 1 -5.486,-1.27; 2 -2.743,-1.27; 3 0,-1.27; 4 2.743,-1.27; 5 5.486,-1.27; 6 -4.115,1.27; 7 -1.372,1.27; 8 1.372,1.27; 9 4.115,1.27 | drill 3.302 pad 5.08 round: G1 -12.522,0; G2 12.522,0
USB-B-H = drill 0.914 round: D+ 0,1.25; D- 1.981,1.25; GND 0,-1.25; VBUS 1.981,-1.25 | drill 2.286 round: P$1 -2.718,-6.02; P$2 -2.718,6.02
1X04 = drill 1.016 long: 1 -3.81,0; 2 -1.27,0; 3 1.27,0; 4 3.81,0

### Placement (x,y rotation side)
AGND  8.89,36.83 0 top
AREF  8.89,30.48 0 top
AVCC  8.89,24.13 0 top
BRD_CON  60.96,59.69 0 top
C1  13.97,69.85 180 top
C2  13.97,66.04 90 top
C3  8.89,66.04 90 top
C4  15.24,87.63 180 top
C5  15.24,82.55 180 top
C6  116.84,33.66 180 top
C7  111.76,33.66 0 top
C8  46.35,34.29 90 top
C9  41.66,17.27 180 top
C10  49.78,20.07 0 top
C11  54.86,25.4 90 top
C12  60.71,19.94 270 top
C13  74.93,16.51 0 top
C14  52.58,15.24 180 top
COMPARATOR  8.89,16.51 0 top
D1  13.97,73.66 180 top
D2  15.24,91.44 180 top
EXTBRD_H1  25.4,21.59 0 top
EXTBRD_H2  154.94,76.2 0 top
EXTBRD_H3  154.94,21.59 0 top
EXTBRD_H4  25.4,76.2 0 top
H1  154.94,95.25 0 top
H2  154.94,5.08 0 top
H3  5.08,5.08 0 top
H4  5.08,95.25 0 top
IC1  29.21,67.31 270 top
IC2  30.48,85.09 270 top
IC3  109.22,59.05 0 top
IC4  41.91,26.16 0 bottom
IC5  67.31,24.13 270 bottom
JTAG_6  151.13,45.72 90 top
JTAG_10  151.13,62.23 270 top
LED1  14.48,60.96 180 top
LED2  15.24,78.74 180 top
LED3  111.76,96.52 0 top
LED4  116.84,96.52 0 top
LED5  121.92,96.52 0 top
LED6  127,96.52 0 top
LED7  132.08,96.52 0 top
LED8  137.16,96.52 0 top
LED9  142.24,96.52 0 top
LED10  147.32,96.52 0 top
LED11  73.66,96.52 0 top
LED12  78.74,96.52 0 top
LED13  83.82,96.52 0 top
LED14  88.9,96.52 0 top
LED15  93.98,96.52 0 top
LED16  99.06,96.52 0 top
LED17  104.14,96.52 0 top
LED18  121.92,3.81 180 top
LED19  116.84,3.81 180 top
LED20  111.76,3.81 180 top
LED21  106.68,3.81 180 top
LED22  101.6,3.81 180 top
LED23  96.52,3.81 180 top
LED24  91.44,3.81 180 top
LED25  86.36,3.81 180 top
PORTB  119.38,70.48 180 top
PORTC  97.79,70.48 180 top
PORTD  104.14,26.67 0 top
Q1  114.3,38.73 0 top
R1  24.13,60.96 0 top
R2  15.24,49.53 180 top
R3  110.49,86.36 270 top
R4  115.57,86.36 270 top
R5  120.65,86.36 270 top
R6  125.73,86.36 270 top
R7  130.81,86.36 270 top
R8  135.89,86.36 270 top
R9  140.97,86.36 270 top
R10  146.05,86.36 270 top
R11  113.03,86.36 270 top
R12  118.11,86.36 270 top
R13  123.19,86.36 270 top
R14  128.27,86.36 270 top
R15  133.35,86.36 270 top
R16  138.43,86.36 270 top
R17  143.51,86.36 270 top
R18  148.59,86.36 270 top
R19  72.39,86.36 270 top
R20  77.47,86.36 270 top
R21  82.55,86.36 270 top
R22  87.63,86.36 270 top
R23  92.71,86.36 270 top
R24  97.79,86.36 270 top
R25  102.87,86.36 270 top
R26  123.19,13.97 90 top
R27  74.93,86.36 270 top
R28  80.01,86.36 270 top
R29  85.09,86.36 270 top
R30  90.17,86.36 270 top
R31  95.25,86.36 270 top
R32  100.33,86.36 270 top
R33  105.41,86.36 270 top
R34  118.11,13.97 90 top
R35  113.03,13.97 90 top
R36  107.95,13.97 90 top
R37  102.87,13.97 90 top
R38  97.79,13.97 90 top
R39  92.71,13.97 90 top
R40  87.63,13.97 90 top
R41  120.65,13.97 90 top
R42  115.57,13.97 90 top
R43  110.49,13.97 90 top
R44  105.41,13.97 90 top
R45  100.33,13.97 90 top
R46  95.25,13.97 90 top
R47  90.17,13.97 90 top
R48  85.09,13.97 90 top
R49  69.85,16.51 0 top
R50  71.12,35.56 0 top
R51  71.12,38.1 0 top
RS232  25.4,8.89 270 bottom
RXLED  59.69,31.75 270 top
S1  15.75,43.94 180 bottom
SUPPLY  3.81,72.39 90 top
TXLED  64.77,31.75 270 top
USART  45.72,10.16 180 top
USB  71.12,10.16 90 top
VOLTAGE  8.89,54.61 180 top
VOUT  31.75,93.34 0 top
XTAL  114.3,46.99 270 top

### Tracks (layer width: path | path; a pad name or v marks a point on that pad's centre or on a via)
+3V3
  Bottom 1.016: LED2.A 16.51,73.03 15.24,71.75 12.06,71.75 10.79,70.48 10.79,69.85 10.16,69.22 7.62,69.22 6.35,67.94 6.35,62.87 4.45,60.96 4.45,56.52 VOLTAGE.3 | IC2.3 29.21,82.55 30.48,83.82 VOUT.2
  Bottom 1.27: IC2.3 C5.1 LED2.A
+5V  (via drill 0.5 pad 0.81)
  Top 0.61: v46.99,57.15 v52.07,57.15
  Bottom 1.016: 31.11,57.15 v46.99,57.15 | VOUT.3 33.02,90.17 34.29,88.9 37.47,88.9 38.73,87.63 38.73,61.59 38.1,60.96 R1.2 | v52.07,57.15 BRD_CON.3
  Bottom 1.27: 11.43,64.77 C3.+ | 11.43,64.77 C2.1 IC1.3 26.67,64.77 R1.2 30.48,57.78 31.11,57.15 | VOLTAGE.1 11.43,64.77
AGND  (via drill 0.5 pad 0.81)
  Top 0.61: v46.99,50.8 v52.07,50.8 | v81.28,47.62 v81.28,55.24 | v81.28,59.05 v81.28,64.77 | v88.27,66.67 v107.95,66.67
  Bottom 0.61: v52.07,50.8 59.69,50.8 62.87,47.62 v81.28,47.62
  Bottom 0.813: v46.99,50.8 45.09,52.7 24.77,52.7 23.5,51.44 23.5,40.01 22.86,39.37 9.53,39.37 8.89,38.73 AGND.2 | v81.28,55.24 v81.28,59.05
  Bottom 1.016: v107.95,66.67 IC3.22 | v81.28,64.77 81.28,66.04 81.92,66.67 v88.27,66.67
AGND_MAN
  Bottom 0.813: AGND.3 11.43,34.92 10.79,34.29 3.17,34.29 2.54,33.66 2.54,12.7 3.17,12.06 10.79,12.06 11.43,12.7 COMPARATOR.3
AREF  (via drill 0.5 pad 0.81)
  Top 0.61: v46.99,48.9 v52.07,48.9 | v83.19,47.62 v83.19,55.24 | v83.19,59.05 v83.19,64.77 | v88.27,64.77 v110.49,64.77
  Bottom 0.61: v52.07,48.9 59.69,48.9 62.23,46.35 82.55,46.35 83.19,46.99 v83.19,47.62
  Bottom 0.813: AREF.2 8.89,31.75 10.16,33.02 12.06,33.02 13.97,34.92 13.97,37.47 14.61,38.1 23.5,38.1 24.77,39.37 24.77,50.16 26.04,51.44 43.81,51.44 46.35,48.9 v46.99,48.9 | v83.19,55.24 v83.19,59.05
  Bottom 1.016: v83.19,64.77 v88.27,64.77 | v110.49,64.77 IC3.21
AREF_MAN
  Bottom 0.813: AREF.1 4.45,30.48 3.81,29.84 3.81,13.97 4.45,13.34 8.26,13.34 8.89,13.97 COMPARATOR.2
AVCC  (via drill 0.5 pad 0.81)
  Top 0.61: v46.99,46.99 v52.07,46.99 | v85.09,47.62 v85.09,55.24
  Bottom 0.61: v52.07,46.99 59.05,46.99 60.96,45.09 84.45,45.09 85.09,45.72 v85.09,47.62
  Bottom 0.813: v46.99,46.99 45.72,46.99 42.55,50.16 27.3,50.16 26.04,48.9 26.04,38.73 24.13,36.83 15.88,36.83 15.24,36.2 15.24,34.29 13.97,33.02 13.97,22.23 13.34,21.59 9.53,21.59 8.89,22.23 AVCC.2 | v85.09,55.24 85.09,58.42 85.72,59.05 112.39,59.05 113.03,59.69 IC3.20
AVCC_MAN
  Bottom 0.813: COMPARATOR.1 AVCC.1
D+
  Bottom 0.406: IC5.15 63.69,18.86 63.75,18.8
  Bottom 1.016: USB.D+ 64.52,10.16 63.75,10.92 63.75,18.8
D-
  Bottom 0.406: IC5.16 64.79,20.55 65.28,20.07
  Bottom 0.61: 65.28,18.54 65.28,20.07
  Bottom 1.016: 65.28,18.54 65.28,12.95 66.04,12.19 69.82,12.19 USB.D-
GND  (via drill 0.5 pad 0.81, 0.6, 0.6 pad 1.02)  (2 unrouted)
  Top 0.61: v28.57,59.05 v33.02,59.05 | v17.78,53.34 v17.78,59.05 | v8.89,59.05 v13.34,59.05 | v89.53,36.2 v107.95,36.2 | v51.44,31.11 v51.44,36.2 | v51.44,24.77 v51.44,29.21 | v1.91,59.05 v6.35,59.05 | v58.17,20.57 v58.17,24.64
  Top 1.016: v81.28,1.27 v81.28,25.4
  Bottom 0.406: IC5.18 62.22,21.86 61.72,22.35 59.69,22.35 58.93,21.59 | IC5.7 71.81,24.45 72.64,23.62 | 60.27,24.06 60.27,23.8 IC5.21 65.46,23.8 65.79,24.13 65.79,26.42 65.78,26.41 IC5.25 IC5.26 | 60.2,23.88 59.69,24.38 59.18,24.38 58.93,24.64 | 69.34,19.56 69.6,19.56 70.36,18.8 70.87,18.8
  Bottom 0.813: 44.96,30.48 44.96,29.72 45.47,29.21 51.31,29.21 | C11.+ 56.9,24.13 57.91,25.15
  pour Bottom (isolate 0.61): 0,0 0,100.33 160.02,100.33 160.02,0
N$1
  Bottom 1.27: D2.C IC2.1 C4.1
N$2
  Bottom 0.61: 44.96,17.27 43.69,18.54 43.69,21.13 IC4.3
  Bottom 0.813: C14.- 50.8,15.24 49.53,16.51 45.72,16.51 44.96,17.27
N$3
  Bottom 0.813: XTAL.5 113.03,40.01 Q1.1 111.76,34.92 C7.1
N$4
  Bottom 1.27: D1.C IC1.1 C1.1
N$5
  Bottom 1.27: LED1.A R1.1
N$6
  Bottom 0.813: XTAL.6 115.57,40.01 Q1.2 116.84,34.92 C6.1
N$7
  Bottom 1.016: R7.1 LED7.A
N$8
  Bottom 1.016: R9.1 LED9.A
N$9
  Bottom 1.016: R10.1 LED10.A
N$10
  Bottom 1.016: R8.1 LED8.A
N$11
  Bottom 1.016: R6.1 LED6.A
N$12
  Bottom 1.016: R5.1 LED5.A
N$13
  Bottom 1.016: R4.1 LED4.A
N$14
  Bottom 1.016: R3.1 LED3.A
N$15
  Bottom 0.406: 49.78,18.54 49.78,21.08 49.28,21.59 46.69,21.59 IC4.1
  Bottom 0.61: C14.+ 53.85,15.49 52.07,17.27 51.05,17.27 49.78,18.54
N$16
  Bottom 1.016: R23.1 LED15.A
N$17
  Bottom 1.016: R25.1 LED17.A
N$18
  Bottom 1.016: LED22.A R37.1
N$19
  Bottom 1.016: R24.1 LED16.A
N$20
  Bottom 1.016: R22.1 LED14.A
N$21
  Bottom 1.016: R21.1 LED13.A
N$22
  Bottom 1.016: R20.1 LED12.A
N$23
  Bottom 1.016: R19.1 LED11.A
N$25
  Bottom 1.016: LED24.A R39.1
N$26
  Bottom 1.016: LED25.A R40.1
N$27
  Bottom 1.016: LED23.A R38.1
N$28
  Bottom 1.016: LED21.A R36.1
N$29
  Bottom 1.016: LED20.A R35.1
N$30
  Bottom 1.016: LED19.A R34.1
N$31
  Bottom 1.016: LED18.A R26.1
N$33
  Bottom 0.61: 45.09,19.05 IC4.2
  Bottom 0.813: 45.09,19.05 47.5,19.05 C10.+
N$34
  Bottom 0.61: IC4.6 40.01,23.5
  Bottom 0.813: 40.01,23.5 40.01,26.04 40.64,26.67 C11.-
N$35
  Bottom 0.61: 42.55,18.92 IC4.4
  Bottom 0.813: 42.55,18.92 42.55,17.65 C9.+
N$36
  Bottom 0.61: 41.27,19.05 IC4.5
  Bottom 0.813: 41.27,19.05 40.89,19.05 40.39,18.54 C9.-
N$37
  Bottom 0.406: IC5.19 65.12,22.5 65.53,22.1 65.53,21.59 66.8,20.32 66.8,18.8
  Bottom 1.016: 66.8,18.8 66.8,17.27 67.56,16.51 R49.1
N$38
  Bottom 0.406: IC5.17 C12.1
N$41
  Bottom 0.813: TXLED.A R50.1
N$42
  Bottom 0.813: R51.1 63.5,38.1 62.87,37.47 62.87,35.56 62.23,34.92 60.33,34.92 59.69,34.29 RXLED.A
N$43
  Bottom 0.406: IC5.23 62.52,25.11 61.98,25.65
  Bottom 0.813: 61.98,25.65 61.98,30.23 62.23,30.48 TXLED.K
N$44
  Bottom 0.406: IC5.22 61.27,24.45 60.33,25.4
  Bottom 1.016: 60.33,25.4 60.33,29.84 RXLED.K
PB0  (via drill 0.5 pad 0.81)
  Top 0.61: v128.27,55.24 v128.27,62.87
  Bottom 0.813: PORTB.1 145.41,70.48 146.05,71.12 R10.2 | IC3.14 v128.27,55.24
  Bottom 1.016: R10.2 R18.2 | v128.27,62.87 PORTB.1
PB1
  Bottom 0.813: PORTB.2 125.73,72.39 126.36,73.03 140.34,73.03 140.97,73.66 R9.2
  Bottom 1.016: R9.2 R17.2 | IC3.15 PORTB.2
PB2
  Bottom 0.813: PORTB.3 123.19,73.66 123.83,74.3 135.25,74.3 135.89,74.93 R8.2
  Bottom 1.016: R8.2 R16.2 | IC3.16 PORTB.3
PB3  (via drill 0.5 pad 0.81)
  Top 0.61: v139.06,60.33 v139.06,62.87 | v140.34,60.33 v140.34,51.44
  Bottom 0.813: PORTB.4 120.65,74.93 121.28,75.56 130.18,75.56 130.81,76.2 R7.2 | IC3.17 120.65,60.96 121.28,60.33 v139.06,60.33 v140.34,60.33 | JTAG_6.4 140.97,46.99 140.34,47.62 v140.34,51.44 | JTAG_10.1 148.59,67.31 147.32,66.04 147.32,63.5 146.69,62.87 v139.06,62.87
  Bottom 1.016: R7.2 R15.2 | IC3.17 PORTB.4
PB4  (via drill 0.5 pad 0.81)
  Top 0.61: v134.62,62.87 v134.62,55.24 | v118.11,64.77 v134.62,64.77
  Bottom 0.61: v134.62,64.77 v134.62,62.87
  Bottom 0.813: PORTB.5 118.11,76.2 118.75,76.83 125.09,76.83 125.73,77.47 R6.2 | v134.62,55.24 148.59,55.24 | 148.59,55.24 149.22,55.24 149.86,55.88 JTAG_10.9 | JTAG_6.5 149.22,49.53 148.59,50.16 148.59,55.24
  Bottom 1.016: R6.2 R14.2 | IC3.18 v118.11,64.77 PORTB.5
PB5
  Bottom 0.813: PORTB.6 115.57,77.47 116.2,78.11 120.02,78.11 120.65,78.74 R5.2 | 139.06,59.05 116.2,59.05 115.57,59.69 IC3.19 | JTAG_6.2 135.25,41.91 133.35,43.81 133.35,55.88 133.99,56.52 138.43,56.52 139.06,57.15 139.06,59.05 | 139.06,59.05 147.32,59.05 147.96,59.69 JTAG_10.7
  Bottom 1.016: R5.2 R13.2 | IC3.19 PORTB.6
PB6  (via drill 0.5 pad 0.81)
  Top 0.61: v132.08,67.94 v113.03,67.94 | v132.08,55.24 v132.08,62.87 | v113.03,52.07 v132.08,52.07
  Bottom 0.813: PORTB.7 113.03,77.47 R4.2 | IC3.9 v113.03,52.07 XTAL.1 XTAL.3 | v132.08,52.07 v132.08,55.24
  Bottom 1.016: R4.2 R12.2 | v113.03,67.94 PORTB.7 | v132.08,62.87 v132.08,67.94
PB7  (via drill 0.5 pad 0.81)
  Top 0.61: v115.57,53.34 v130.18,53.34 | v130.18,55.24 v130.18,62.87 | v130.18,66.67 v110.49,66.67
  Bottom 0.813: PORTB.8 R3.2 | IC3.10 v115.57,53.34 XTAL.2 XTAL.4 | v130.18,53.34 v130.18,55.24
  Bottom 1.016: R3.2 R11.2 | v110.49,66.67 PORTB.8 | v130.18,62.87 v130.18,66.67
PC0
  Bottom 1.016: R25.2 R33.2 PORTC.1 IC3.23
  Bottom 1.27: BRD_CON.9 67.31,67.31 62.87,71.75 62.87,87 64.14,88.27 101.6,88.27 102.87,87 R25.2
PC1
  Bottom 0.813: PORTC.2 102.87,77.47 R32.2
  Bottom 1.016: R24.2 R32.2 | PORTC.2 IC3.24
  Bottom 1.27: BRD_CON.10 69.85,67.94 65.41,72.39 65.41,85.09 66.67,86.36 96.52,86.36 97.79,85.09 R24.2
PC2
  Bottom 0.813: R23.2 R31.2 95.25,78.74 95.89,78.11 99.69,78.11 100.33,77.47 PORTC.3
  Bottom 1.016: PORTC.3 IC3.25
  Bottom 1.27: BRD_CON.11 72.39,68.58 67.94,73.03 67.94,83.19 69.22,84.45 92.08,84.45 92.71,83.82 R23.2
PC3
  Bottom 0.813: PORTC.4 97.79,76.2 97.16,76.83 90.81,76.83 90.17,77.47 R30.2
  Bottom 1.016: R22.2 R30.2 | PORTC.4 IC3.26
  Bottom 1.27: BRD_CON.12 74.93,69.22 70.48,73.66 70.48,81.28 71.75,82.55 87,82.55 87.63,81.92 R22.2
PC4  (via drill 0.5 pad 0.81)
  Top 0.61: v57.15,55.24 v67.31,55.24
  Bottom 0.813: PORTC.5 95.25,74.93 94.61,75.56 85.72,75.56 85.09,76.2 R29.2 | v67.31,55.24 77.47,55.24 79.38,57.15 79.38,59.69 80.01,60.33 94.61,60.33 95.25,60.96 IC3.27
  Bottom 1.016: R29.2 R21.2 | IC3.27 PORTC.5 | BRD_CON.4 54.61,55.88 55.24,55.24 v57.15,55.24
PC5  (via drill 0.5 pad 0.81)
  Top 0.61: v57.15,57.15 v67.31,57.15
  Bottom 0.61: 92.71,62.23 IC3.28
  Bottom 0.813: PORTC.6 92.71,73.66 92.08,74.3 80.64,74.3 80.01,74.93 R28.2 | v67.31,57.15 76.83,57.15 78.11,58.42 78.11,60.33 79.38,61.59 92.08,61.59 92.71,62.23
  Bottom 1.016: R28.2 R20.2 | IC3.28 PORTC.6 | v57.15,57.15 BRD_CON.5
PC6  (via drill 0.5 pad 0.81)
  Top 0.61: v90.17,55.24 v90.17,62.87 | v46.99,53.98 v67.31,53.98 | v137.16,57.78 v137.16,62.87 | v135.89,57.78 v135.89,53.34
  Bottom 0.61: S1.1 10.97,41.91
  Bottom 0.813: PORTC.7 90.17,72.39 89.53,73.03 75.56,73.03 74.93,73.66 R27.2 | R2.1 21.59,53.34 22.23,53.98 v46.99,53.98 | v67.31,53.98 89.53,53.98 90.17,54.61 v90.17,55.24 IC3.1 92.71,57.15 93.34,57.78 v135.89,57.78 v137.16,57.78 | v135.89,53.34 135.89,45.09 136.53,44.45 JTAG_6.3 | v137.16,62.87 137.16,62.23 137.79,61.59 147.96,61.59 148.59,62.23 JTAG_10.5
  Bottom 1.016: R27.2 R19.2 | v90.17,62.87 PORTC.7
  Bottom 1.27: 10.97,41.91 15.24,41.91 15.88,42.55 15.88,48.9 16.51,49.53 R2.1
PD0
  Bottom 0.813: R40.2 87.63,22.61 88.65,23.62 94.23,23.62 95.25,24.64 PORTD.1 IC3.2
  Bottom 1.016: RS232.6 24.13,3.81 25.15,2.79 80.77,2.79 82.55,4.57 82.55,19.81 83.06,20.32 R48.2 R40.2
PD1  (via drill 0.6 pad 1.02)
  Top 0.61: v84.07,22.61 96.77,22.61 v96.9,22.73
  Bottom 0.61: R39.2 R47.2
  Bottom 0.813: R39.2 94.49,22.1 96.27,22.1 v96.9,22.73 97.79,23.62 PORTD.2 IC3.3
  Bottom 1.016: RS232.5 28.7,4.32 79.76,4.32 80.52,5.08 80.52,21.08 82.04,22.61 v84.07,22.61
PD2  (via drill 0.5 pad 0.81)
  Top 0.61: v59.69,52.7 v67.31,52.7 | v92.71,52.7 v100.33,52.7
  Bottom 0.61: R38.2 R46.2
  Bottom 0.813: v67.31,52.7 v92.71,52.7 | R38.2 100.33,22.86 PORTD.3 v100.33,52.7 IC3.4
  Bottom 1.016: v59.69,52.7 BRD_CON.6
PD3
  Bottom 0.61: R45.2 R37.2
  Bottom 0.813: R37.2 PORTD.4 IC3.5
PD4
  Bottom 0.61: R44.2 R36.2
  Bottom 0.813: R44.2 PORTD.5 IC3.6
PD5
  Bottom 0.61: R43.2 R35.2
  Bottom 0.813: R43.2 107.95,22.86 PORTD.6 107.95,29.84 108.58,30.48 119.38,30.48 120.02,31.11 120.02,40.01 118.11,41.91 IC3.11
PD6  (via drill 0.5 pad 0.81)
  Top 0.61: v92.71,31.11 v121.28,31.11
  Bottom 0.61: R42.2 R34.2
  Bottom 0.813: 64.77,52.7 64.77,51.44 65.41,50.8 92.08,50.8 92.71,50.16 v92.71,31.11 | R42.2 115.57,21.59 114.81,22.35 111.76,22.35 110.49,23.62 PORTD.7 110.49,27.94 111.76,29.21 120.65,29.21 121.28,29.84 v121.28,31.11 121.28,41.27 120.65,41.91 IC3.12
  Bottom 1.016: 64.77,52.7 BRD_CON.8
PD7  (via drill 0.5 pad 0.81)
  Top 0.61: v92.71,29.21 v123.06,29.21
  Bottom 0.61: R41.2 R26.2
  Bottom 0.813: 62.23,52.7 62.23,50.8 63.5,49.53 90.81,49.53 91.44,48.9 91.44,29.84 92.08,29.21 v92.71,29.21 | PORTD.8 113.03,25.4 114.55,23.88 119.63,23.88 | 119.63,23.88 119.89,23.88 120.65,23.11 R41.2 | 119.63,23.88 122.56,26.8 122.56,28.7 v123.06,29.21 123.06,55.12 IC3.13
  Bottom 1.016: 62.23,52.7 BRD_CON.7
R2IN
  Bottom 0.61: 37.47,19.3 IC4.8
  Bottom 0.813: USART.3 45.72,12.95 45.34,13.34 38.1,13.34 37.47,13.97 37.47,19.3
RXD  (via drill 0.5 pad 0.81)
  Top 0.61: v72.9,27.94 v72.9,25.15
  Bottom 0.406: IC5.5 72.29,25.75 v72.9,25.15 | 43.81,34.29 48.9,34.29
  Bottom 0.61: 35.56,29.84 36.83,29.84 37.47,30.48 IC4.9 37.47,33.66
  Bottom 0.813: v72.9,27.94 72.9,31.88 71.75,33.02 69.22,33.02 68.58,33.66 68.58,39.37 67.94,40.01 62.23,40.01 60.96,38.73 60.96,37.47 60.33,36.83 58.42,36.83 55.88,34.29 48.9,34.29 | 37.47,33.66 38.1,34.29 43.81,34.29
  Bottom 1.016: RS232.4 22.1,8.89 21.59,9.4 21.59,12.7 22.61,13.72 26.16,13.72 26.92,14.48 26.92,15.75 28.19,17.02 33.02,17.02 33.78,17.78 33.78,29.21 34.42,29.84 35.56,29.84
T2OUT
  Bottom 0.61: 38.73,19.3 IC4.7
  Bottom 0.813: USART.2 48.51,11.48 48.51,13.97 47.88,14.61 39.37,14.61 38.73,15.24 38.73,19.3
TXD
  Bottom 0.406: 70.36,31.75 70.87,31.24 70.87,28.42 IC5.1
  Bottom 0.61: 36.2,28.57 38.1,28.57 38.73,29.21 | 38.73,29.21 IC4.10 | 38.73,29.21 38.73,29.08 | 57.66,31.75 66.67,31.75
  Bottom 0.813: 38.73,29.08 38.86,29.08 40.01,27.94 53.34,27.94 53.98,28.57 56.52,28.57 57.15,29.21 57.15,31.24 57.66,31.75 | 66.67,31.75 70.36,31.75
  Bottom 1.016: RS232.3 28.45,8.89 28.7,9.14 28.7,14.99 28.96,15.24 34.54,15.24 35.56,16.26 35.56,27.94 36.2,28.57
V+
  Bottom 1.27: SUPPLY.2 D1.A 8.89,90.17 D2.A
VCC  (via drill 0.5 pad 0.81)
  Top 0.61: v1.27,27.94 v5.08,27.94 | v49.53,40.01 v49.53,32.38 | v49.53,31.11 v49.53,24.77 | v107.95,42.55 v125.09,42.55 | v87,41.27 v107.95,41.27 | v132.08,50.16 v137.79,50.16 | v142.24,53.34 v142.24,64.14
  Bottom 0.406: IC5.4 70.95,26.42 74.17,26.42 74.42,26.16 | 57.95,23.16 IC5.20 65.49,23.16 66.29,22.35 66.29,21.84 68.07,20.07 68.07,18.54 68.33,18.29
  Bottom 0.61: 8.89,49.28 R2.2 | 49.48,31.06 IC4.16 C8.+ | v49.53,32.38 49.48,31.06 | 49.48,31.06 v49.53,31.11
  Bottom 0.813: BRD_CON.2 49.53,55.88 48.9,55.24 15.88,55.24 13.97,53.34 13.97,50.8 12.7,49.53 R2.2 | 11.43,27.94 AVCC.3 | 11.43,27.94 AREF.3 | v5.08,27.94 11.43,27.94 | 8.89,49.28 2.29,49.28 1.27,48.26 v1.27,27.94 | v87,41.27 78.11,41.27 77.47,40.64 R51.2 R50.2 77.47,27.3 76.2,26.04 74.55,26.04 74.42,26.16 74.42,17.27 C13.1 | 68.33,18.29 69.34,18.29 R49.2 | 57.95,23.16 57.02,22.23 51.05,22.23 | 51.05,22.23 50.16,22.23 49.53,22.86 v49.53,24.77 | v107.95,41.27 v107.95,42.55 IC3.7 | v132.08,50.16 125.73,50.16 125.09,49.53 v125.09,42.55 125.09,40.64 126.36,39.37 JTAG_6.1 | v137.79,50.16 137.79,52.7 138.43,53.34 v142.24,53.34 | v142.24,64.14 145.41,64.14 146.05,64.77 146.05,67.94 147.32,69.22 151.76,69.22 152.4,68.58 JTAG_10.2 | 51.05,22.23 C10.-
  Bottom 1.016: VOUT.4 35.56,92.08 36.83,90.81 38.73,90.81 40.64,88.9 40.64,63.5 41.27,62.87 48.9,62.87 49.53,62.23 BRD_CON.2 | R49.2 72.39,16.51 | 72.39,16.51 C13.1 | USB.VBUS 72.37,16.49 72.39,16.51 | 49.53,55.88 v49.53,40.01
  Bottom 1.27: R2.2 VOLTAGE.2

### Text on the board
Bottom: 3.3V | 5V | Vcc | VOUT | PROTC | 6 | 0 | 7 | 0 | PORTB | + | BRD_CON | JTAG | VOLTAGE | RESET | AGND | AREF | AVCC | COMP | PORTD | RS232 | 0 | 7 | V0.1 | by hannes eilers | ATmega Testboard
